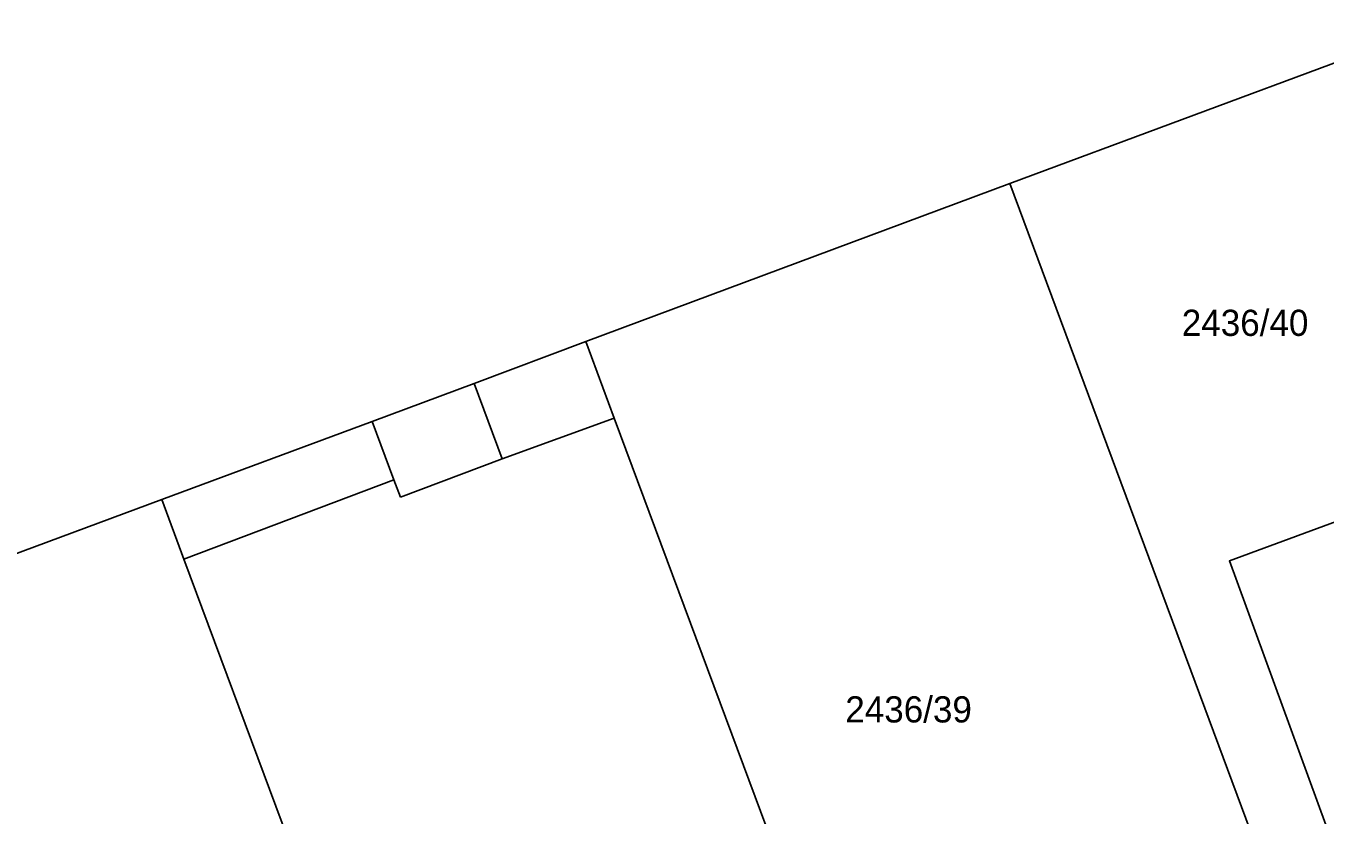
# Model space of a CAD drawing. Extents: x -566117 to -565580, y -1202428 to -1201938.
# Drawn here: x -565883.9 to -565829.4, y -1201990.4 to -1201957.3 of the extents above; entities that cross this region are included whole.
import ezdxf

# ---------------------------------------------------------------- set-up
doc = ezdxf.new("R2010")
doc.units = 0
for name, color, linetype in [('BUOVY_NEMĚŘ', 7, 'Continuous'), ('Implicitní', 7, 'Continuous'), ('Katastr', 7, 'Continuous'), ('Zpevněné plohy', 7, 'Continuous')]:
    doc.layers.add(name, color=color, linetype=linetype)

# ---------------------------------------------------------------- blocks, each defined once
blk = doc.blocks.new('A$C69D74C1E')
at = {"layer": 'Katastr'}
for p, q in [((222.34, 104.51), (240.15, 111.13)), ((204.53, 97.88), (222.34, 104.51)), ((239.78, 57.64), (222.34, 104.51)), ((201.03, 92.95), (199.85, 96.12)), ((196.47, 92.08), (195.57, 94.52)), ((201.03, 92.95), (205.73, 94.66)), ((196.75, 91.35), (201.03, 92.95)), ((187.66, 88.74), (196.47, 92.08)), ((196.47, 92.08), (196.75, 91.35)), ((168.92, 84.62), (186.73, 91.25))]:
    blk.add_line(p, q, dxfattribs=at)
for points in [[(186.73, 91.25), (195.57, 94.52), (199.85, 96.12), (204.53, 97.88)], [(204.53, 97.88), (205.73, 94.66), (221.98, 51.03)], [(204.17, 44.4), (187.66, 88.74), (186.73, 91.25)], [(235.99, 76.56), (231.56, 88.67), (237.22, 90.76), (238.6, 87.02), (244.96, 89.37), (246.11, 86.16), (246.26, 86.22), (248.02, 81.58), (248.72, 81.86), (249.73, 79.12), (249.03, 78.86), (252.43, 69.69), (246.53, 67.52), (247.06, 66.11), (240.65, 63.73), (235.89, 76.52), (235.99, 76.56)]]:
    blk.add_lwpolyline(points, dxfattribs=at)
for s, p in [('2436/40', (229.56, 98.117)), ('2436/39', (215.43, 81.887))]:
    blk.add_text(s, height=1.1, dxfattribs=at).set_placement(p)

msp = doc.modelspace()

# ---------------------------------------------------------------- linework, layer by layer
at = {"layer": 'BUOVY_NEMĚŘ'}
msp.add_lwpolyline([(-565827.71, -1201977.68), (-565826.33, -1201981.42), (-565819.97, -1201979.07), (-565818.82, -1201982.28), (-565818.67, -1201982.22), (-565816.91, -1201986.86), (-565816.21, -1201986.58), (-565815.2, -1201989.32), (-565815.9, -1201989.58), (-565812.5, -1201998.75), (-565818.4, -1202000.92), (-565817.87, -1202002.33), (-565824.28, -1202004.71), (-565829.04, -1201991.92), (-565828.94, -1201991.88), (-565833.37, -1201979.77), (-565827.71, -1201977.68)], dxfattribs=at)
at = {"layer": 'Zpevněné plohy'}
msp.add_open_spline([(-566046.233, -1202095.491), (-566045.931, -1202095.393), (-566043.978, -1202094.752), (-566040.389, -1202093.195), (-566035.531, -1202091.756), (-566028.975, -1202089.449), (-566022.404, -1202086.74), (-566013.877, -1202083.764), (-566006.988, -1202080.967), (-565999.231, -1202078.336), (-565993.39, -1202076.098), (-565982.391, -1202071.759), (-565967.94, -1202066.641), (-565949.498, -1202059.811), (-565935.388, -1202054.572), (-565926.049, -1202051.077), (-565917.958, -1202048.181), (-565909.827, -1202045.163), (-565898.95, -1202041.321), (-565888.732, -1202037.388), (-565879.759, -1202034.036), (-565869.081, -1202030.224), (-565859.242, -1202026.317), (-565849.297, -1202023.069), (-565843.932, -1202020.848), (-565836.631, -1202018.501), (-565830.04, -1202016.01), (-565822.89, -1202013.251), (-565816.476, -1202011.009), (-565808.989, -1202007.913), (-565802.143, -1202004.887), (-565798.059, -1202002.759), (-565793.947, -1202000.116), (-565789.34, -1201997.072), (-565785.134, -1201994.185), (-565781.539, -1201991.969), (-565778.045, -1201989.73), (-565773.319, -1201986.775), (-565768.281, -1201983.714), (-565761.544, -1201979.725), (-565754.374, -1201977.005), (-565748.201, -1201974.518), (-565743.713, -1201972.786), (-565741.115, -1201971.759), (-565739.444, -1201971.098)], degree=3, dxfattribs=at)

# ---------------------------------------------------------------- block references
at = {"layer": 'Implicitní'}
msp.add_blockref('A$C69D74C1E', (-566064.93, -1202068.44), dxfattribs=at)

doc.saveas('drawing.dxf')
